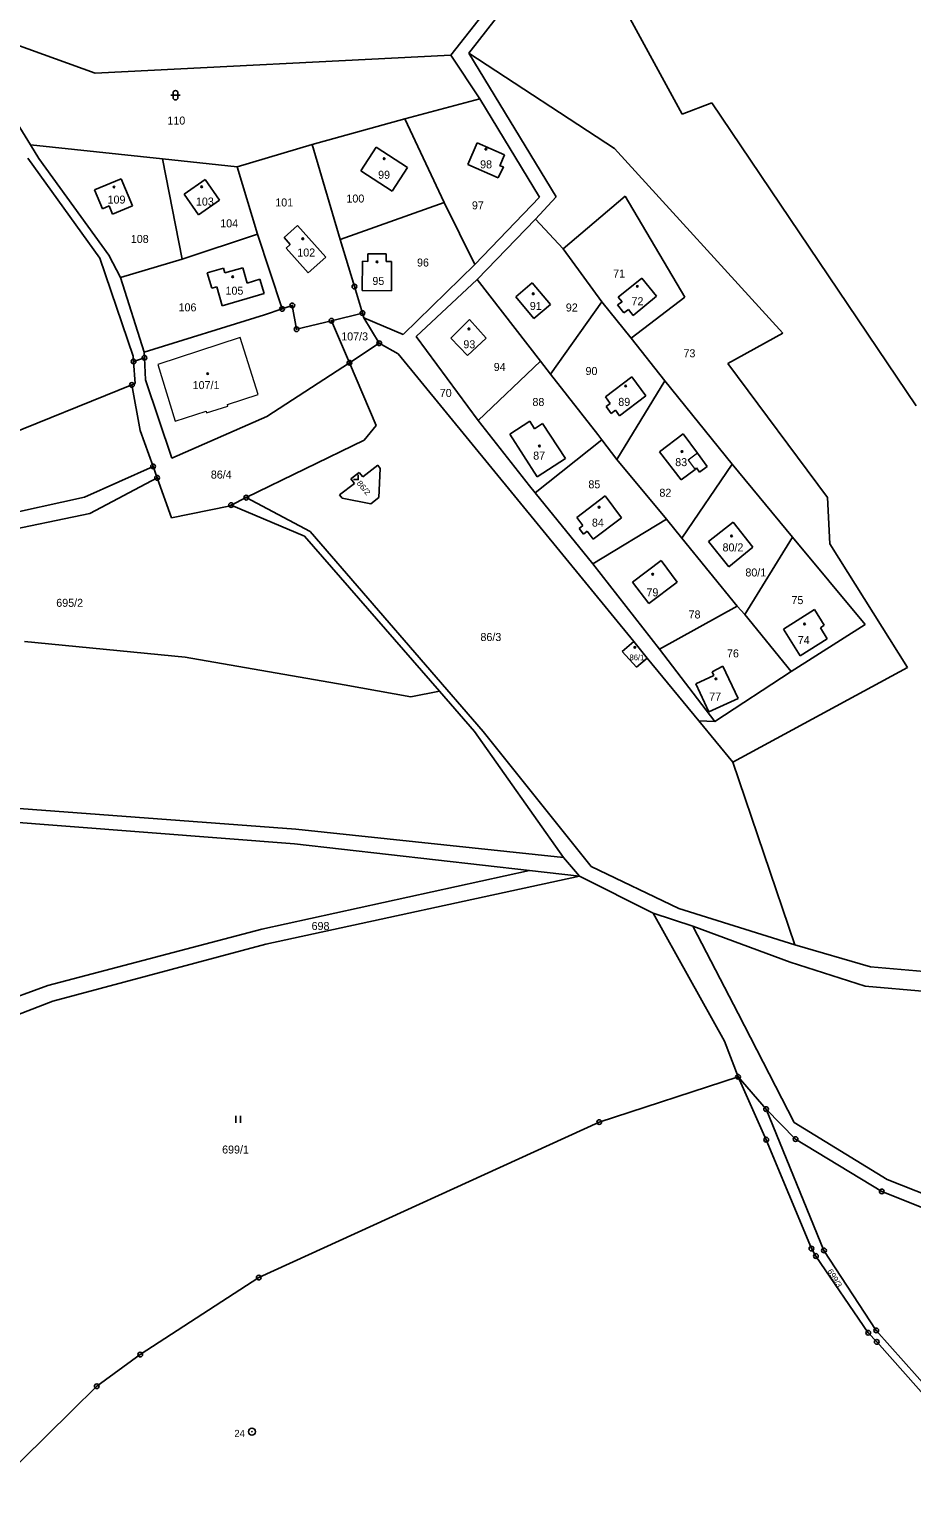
# Model space of a CAD drawing. Extents: x -727701 to -724405, y -960481 to -957284.
# Drawn here: x -726246.1 to -726058.6, y -958595.3 to -958285.9 of the extents above; entities that cross this region are included whole.
import ezdxf
from ezdxf.enums import TextEntityAlignment as Align

# ---------------------------------------------------------------- set-up
doc = ezdxf.new("R2010")
doc.units = 0
doc.header["$LTSCALE"] = 0.68
for name, color, linetype, lineweight in [('1', 7, 'Continuous', 25), ('3', 7, 'Continuous', 25), ('4', 7, 'Continuous', 13), ('5', 7, 'Continuous', 25), ('8', 7, 'Continuous', 25)]:
    doc.layers.add(name, color=color, linetype=linetype, lineweight=lineweight)
doc.layers.add('2', color=7, linetype='Continuous')

msp = doc.modelspace()

# ---------------------------------------------------------------- linework, layer by layer
at = {"layer": '1'}
for p, q in [((-726156.53, -958291.46), (-726131.48, -958259.62)), ((-726130.22, -958262.09), (-726152.69, -958291.05)), ((-726107.42, -958304.01), (-726130.22, -958262.09)), ((-726248.92, -958289.17), (-726232.04, -958295.26)), ((-726232.04, -958295.26), (-726156.53, -958291.46)), ((-726156.53, -958291.46), (-726150.4, -958300.7)), ((-726152.69, -958291.05), (-726121.8, -958311.26)), ((-726152.69, -958291.05), (-726134.14, -958321.53)), ((-726252.3, -958300), (-726245.81, -958310.48)), ((-726150.4, -958300.7), (-726166.3, -958305)), ((-726150.4, -958300.7), (-726137.68, -958321.61)), ((-726101.1, -958301.58), (-726107.42, -958304.01)), ((-726101.1, -958301.58), (-726057.73, -958365.9)), ((-726166.3, -958305), (-726186, -958310.45)), ((-726166.3, -958305), (-726157.97, -958322.75)), ((-726245.81, -958310.48), (-726244, -958313.4)), ((-726245.81, -958310.48), (-726217.76, -958313.46)), ((-726186, -958310.45), (-726201.9, -958315.15)), ((-726186, -958310.45), (-726180, -958330.6)), ((-726152.95, -958314.7), (-726150.95, -958310.05)), ((-726150.95, -958310.05), (-726145.15, -958312.65)), ((-726231.1, -958334.55), (-726246.35, -958313.35)), ((-726244, -958313.4), (-726229.15, -958333.9)), ((-726217.76, -958313.46), (-726201.9, -958315.15)), ((-726217.76, -958313.46), (-726213.61, -958334.79)), ((-726175.66, -958316.02), (-726172.41, -958310.97)), ((-726172.41, -958310.97), (-726165.71, -958315.28)), ((-726145.15, -958312.65), (-726146.15, -958314.95)), ((-726121.8, -958311.26), (-726086.04, -958350.49)), ((-726201.9, -958315.15), (-726197.62, -958329.45)), ((-726168.96, -958320.33), (-726175.66, -958316.02)), ((-726165.71, -958315.28), (-726168.96, -958320.33)), ((-726146.45, -958317.5), (-726152.95, -958314.7)), ((-726145.35, -958315.2), (-726146.45, -958317.5)), ((-726146.15, -958314.95), (-726145.35, -958315.2)), ((-726232.17, -958320.08), (-726226.53, -958317.72)), ((-726226.53, -958317.72), (-726224.12, -958323.47)), ((-726213.18, -958320.94), (-726208.73, -958317.88)), ((-726208.73, -958317.88), (-726205.69, -958322.28)), ((-726230.51, -958324.06), (-726232.17, -958320.08)), ((-726210.14, -958325.35), (-726213.18, -958320.94)), ((-726205.69, -958322.28), (-726210.14, -958325.35)), ((-726180, -958330.6), (-726157.97, -958322.75)), ((-726157.97, -958322.75), (-726151.46, -958335.91)), ((-726137.68, -958321.61), (-726151.46, -958335.91)), ((-726134.14, -958321.53), (-726138.53, -958326.25)), ((-726132.7, -958332.6), (-726119.48, -958321.37)), ((-726119.48, -958321.37), (-726106.86, -958342.85)), ((-726229.12, -958323.47), (-726230.51, -958324.06)), ((-726228.38, -958325.25), (-726229.12, -958323.47)), ((-726224.12, -958323.47), (-726228.38, -958325.25)), ((-726191.95, -958330.16), (-726189.12, -958327.62)), ((-726189.12, -958327.62), (-726183.1, -958334.34)), ((-726138.53, -958326.25), (-726150.93, -958339.1)), ((-726138.53, -958326.25), (-726132.7, -958332.6)), ((-726197.62, -958329.45), (-726213.61, -958334.79)), ((-726192.38, -958345.35), (-726197.62, -958329.45)), ((-726190.62, -958331.65), (-726191.95, -958330.16)), ((-726191.51, -958332.45), (-726190.62, -958331.65)), ((-726177, -958340.6), (-726180, -958330.6)), ((-726224, -958355.35), (-726231.1, -958334.55)), ((-726229.15, -958333.9), (-726226.71, -958338.7)), ((-726213.61, -958334.79), (-726226.71, -958338.7)), ((-726186.83, -958337.68), (-726191.51, -958332.45)), ((-726183.1, -958334.34), (-726186.83, -958337.68)), ((-726175.34, -958341.45), (-726175.31, -958335.23)), ((-726175.31, -958335.23), (-726174.17, -958335.24)), ((-726174.17, -958335.24), (-726174.16, -958333.65)), ((-726174.16, -958333.65), (-726170.29, -958333.67)), ((-726170.29, -958333.67), (-726170.29, -958335.26)), ((-726170.29, -958335.26), (-726169.1, -958335.27)), ((-726169.1, -958335.27), (-726169.13, -958341.48)), ((-726132.7, -958332.6), (-726124.5, -958343.85)), ((-726208.24, -958337.69), (-726204.81, -958336.7)), ((-726207.3, -958340.96), (-726208.24, -958337.69)), ((-726204.81, -958336.7), (-726204.52, -958337.7)), ((-726204.52, -958337.7), (-726200.72, -958336.6)), ((-726200.72, -958336.6), (-726199.78, -958339.85)), ((-726151.46, -958335.91), (-726166.67, -958350.8)), ((-726226.71, -958338.7), (-726221.66, -958354.51)), ((-726206.23, -958340.65), (-726207.3, -958340.96)), ((-726205.07, -958344.66), (-726206.23, -958340.65)), ((-726199.78, -958339.85), (-726197.06, -958339.06)), ((-726197.06, -958339.06), (-726196.19, -958342.09)), ((-726177, -958340.6), (-726175.31, -958346.24)), ((-726169.13, -958341.48), (-726175.34, -958341.45)), ((-726150.93, -958339.1), (-726163.91, -958351.18)), ((-726150.93, -958339.1), (-726137.5, -958356.45)), ((-726142.75, -958342.8), (-726139.23, -958339.84)), ((-726139.23, -958339.84), (-726135.36, -958344.43)), ((-726120.97, -958342.84), (-726116, -958338.8)), ((-726116, -958338.8), (-726112.85, -958342.67)), ((-726196.19, -958342.09), (-726205.07, -958344.66)), ((-726192.38, -958345.35), (-726190.19, -958344.6)), ((-726189.3, -958349.67), (-726190.19, -958344.6)), ((-726138.88, -958347.39), (-726142.75, -958342.8)), ((-726135.36, -958344.43), (-726138.88, -958347.39)), ((-726135.35, -958359.2), (-726124.5, -958343.85)), ((-726124.5, -958343.85), (-726118.26, -958351.56)), ((-726121.16, -958344.51), (-726120.14, -958343.85)), ((-726119.81, -958346.16), (-726121.16, -958344.51)), ((-726120.14, -958343.85), (-726120.97, -958342.84)), ((-726106.86, -958342.85), (-726118.26, -958351.56)), ((-726112.85, -958342.67), (-726117.81, -958346.71)), ((-726221.66, -958354.51), (-726196.07, -958346.62)), ((-726196.07, -958346.62), (-726192.38, -958345.35)), ((-726175.31, -958346.24), (-726181.88, -958347.85)), ((-726175.31, -958346.24), (-726175.01, -958347.25)), ((-726175.01, -958347.25), (-726171.72, -958352.65)), ((-726166.67, -958350.8), (-726175.01, -958347.25)), ((-726156.5, -958351.55), (-726152.6, -958347.6)), ((-726152.6, -958347.6), (-726149.05, -958351.55)), ((-726118.82, -958345.47), (-726119.81, -958346.16)), ((-726117.81, -958346.71), (-726118.82, -958345.47)), ((-726181.88, -958347.85), (-726189.3, -958349.67)), ((-726178.07, -958356.78), (-726181.88, -958347.85)), ((-726086.04, -958350.49), (-726097.7, -958356.93)), ((-726171.72, -958352.65), (-726178.07, -958356.78)), ((-726171.72, -958352.65), (-726167.68, -958354.91)), ((-726163.91, -958351.18), (-726150.74, -958369.06)), ((-726153, -958355.25), (-726156.5, -958351.55)), ((-726149.05, -958351.55), (-726153, -958355.25)), ((-726118.26, -958351.56), (-726111.1, -958360.6)), ((-726223.91, -958356.5), (-726224, -958355.35)), ((-726221.61, -958355.72), (-726223.91, -958356.5)), ((-726223.55, -958361.2), (-726223.91, -958356.5)), ((-726221.66, -958354.51), (-726221.61, -958355.72)), ((-726221.61, -958355.72), (-726221.4, -958360.4)), ((-726195.6, -958368.19), (-726178.07, -958356.78)), ((-726172.38, -958370.12), (-726178.07, -958356.78)), ((-726117.66, -958416.01), (-726167.68, -958354.91)), ((-726137.5, -958356.45), (-726150.74, -958369.06)), ((-726137.5, -958356.45), (-726135.35, -958359.2)), ((-726097.7, -958356.93), (-726076.55, -958385.41)), ((-726135.35, -958359.2), (-726125.35, -958372.05)), ((-726123.71, -958364.02), (-726118.13, -958359.79)), ((-726118.13, -958359.79), (-726115.1, -958363.79)), ((-726224.26, -958361.49), (-726337.66, -958407.23)), ((-726224.26, -958361.49), (-726223.55, -958361.2)), ((-726222.49, -958371.17), (-726224.26, -958361.49)), ((-726221.4, -958360.4), (-726215.76, -958377.07)), ((-726121.3, -958377.3), (-726111.1, -958360.6)), ((-726111.1, -958360.6), (-726096.8, -958378.3)), ((-726122.67, -958365.4), (-726123.71, -958364.02)), ((-726123.58, -958366.09), (-726122.67, -958365.4)), ((-726122.49, -958367.54), (-726123.58, -958366.09)), ((-726115.1, -958363.79), (-726120.68, -958368.02)), ((-726195.6, -958368.19), (-726215.76, -958377.07)), ((-726150.74, -958369.06), (-726139.8, -958382.9)), ((-726144, -958371.96), (-726139.78, -958369.15)), ((-726139.78, -958369.15), (-726138.73, -958370.8)), ((-726121.57, -958366.84), (-726122.49, -958367.54)), ((-726120.68, -958368.02), (-726121.57, -958366.84)), ((-726222.49, -958371.17), (-726219.77, -958378.79)), ((-726174.91, -958373.24), (-726172.38, -958370.12)), ((-726138.17, -958381), (-726144, -958371.96)), ((-726138.73, -958370.8), (-726137.07, -958369.7)), ((-726137.07, -958369.7), (-726132.21, -958377.13)), ((-726125.35, -958372.05), (-726124.48, -958373.17)), ((-726112.21, -958375.72), (-726107.21, -958371.86)), ((-726107.21, -958371.86), (-726104.16, -958375.95)), ((-726199.96, -958385.43), (-726174.91, -958373.24)), ((-726124.48, -958373.17), (-726138.61, -958384.37)), ((-726124.48, -958373.17), (-726121.3, -958377.3)), ((-726175.25, -958381.02), (-726172.05, -958378.53)), ((-726172.05, -958378.53), (-726171.51, -958379.23)), ((-726132.21, -958377.13), (-726138.17, -958381)), ((-726121.3, -958377.3), (-726110.75, -958390)), ((-726112.21, -958375.72), (-726107.63, -958381.65)), ((-726107.5, -958394.05), (-726096.8, -958378.3)), ((-726104.16, -958375.95), (-726102.07, -958378.79)), ((-726096.8, -958378.3), (-726083.95, -958393.8)), ((-726234.32, -958385.34), (-726219.77, -958378.79)), ((-726218.9, -958381.22), (-726233.19, -958388.78)), ((-726219.77, -958378.79), (-726218.9, -958381.22)), ((-726218.9, -958381.22), (-726215.86, -958389.72)), ((-726177.75, -958381.45), (-726175.99, -958380.07)), ((-726177, -958382.45), (-726177.75, -958381.45)), ((-726175.99, -958380.07), (-726175.25, -958381.02)), ((-726171.84, -958385.42), (-726171.51, -958379.23)), ((-726104.65, -958379.42), (-726107.63, -958381.65)), ((-726104.35, -958379.13), (-726104.65, -958379.42)), ((-726103.71, -958380), (-726104.35, -958379.13)), ((-726102.07, -958378.79), (-726103.71, -958380)), ((-726180.16, -958384.84), (-726177, -958382.45)), ((-726139.8, -958382.9), (-726138.61, -958384.37)), ((-726138.61, -958384.37), (-726126.4, -958399.45)), ((-726275.59, -958394.37), (-726234.32, -958385.34)), ((-726215.86, -958389.72), (-726203.69, -958387.24)), ((-726203.69, -958387.24), (-726203.2, -958387)), ((-726203.2, -958387), (-726199.96, -958385.43)), ((-726203.2, -958387), (-726187.6, -958393.6)), ((-726186.4, -958392.6), (-726199.96, -958385.43)), ((-726179.62, -958385.54), (-726180.16, -958384.84)), ((-726173.55, -958386.75), (-726179.62, -958385.54)), ((-726171.84, -958385.42), (-726173.55, -958386.75)), ((-726129.8, -958389.63), (-726123.76, -958385.07)), ((-726123.76, -958385.07), (-726120.27, -958389.7)), ((-726076.55, -958385.41), (-726076.03, -958395.25)), ((-726274.62, -958397.41), (-726233.19, -958388.78)), ((-726128.49, -958391.37), (-726129.8, -958389.63)), ((-726110.75, -958390), (-726126.4, -958399.45)), ((-726120.27, -958389.7), (-726126.32, -958394.26)), ((-726110.75, -958390), (-726107.5, -958394.05)), ((-726101.83, -958394.76), (-726096.57, -958390.61)), ((-726096.57, -958390.61), (-726092.38, -958395.92)), ((-726158.93, -958426.55), (-726187.6, -958393.6)), ((-726186.4, -958392.6), (-726149.7, -958435.1)), ((-726129.25, -958391.95), (-726128.49, -958391.37)), ((-726128.34, -958393.15), (-726129.25, -958391.95)), ((-726127.59, -958392.58), (-726128.34, -958393.15)), ((-726126.32, -958394.26), (-726127.59, -958392.58)), ((-726094.1, -958410.25), (-726083.95, -958393.8)), ((-726083.95, -958393.8), (-726068.53, -958412.38)), ((-726097.5, -958400.09), (-726101.83, -958394.76)), ((-726092.38, -958395.92), (-726097.5, -958400.09)), ((-726076.03, -958395.25), (-726059.53, -958421.51)), ((-726126.4, -958399.45), (-726112.25, -958417.6)), ((-726117.94, -958403.35), (-726111.9, -958398.81)), ((-726111.9, -958398.81), (-726108.45, -958403.4)), ((-726114.49, -958407.94), (-726117.94, -958403.35)), ((-726108.45, -958403.4), (-726114.49, -958407.94)), ((-726095.7, -958408.5), (-726112.25, -958417.6)), ((-726085.92, -958413.33), (-726079.34, -958409.19)), ((-726079.34, -958409.19), (-726077.23, -958412.54)), ((-726094.1, -958410.25), (-726084.25, -958422.35)), ((-726068.53, -958412.38), (-726084.25, -958422.35)), ((-726077.23, -958412.54), (-726078.05, -958413.06)), ((-726082.34, -958419.02), (-726085.92, -958413.33)), ((-726076.58, -958415.39), (-726082.34, -958419.02)), ((-726078.05, -958413.06), (-726076.58, -958415.39)), ((-726247.04, -958415.98), (-726212.97, -958419.3)), ((-726120.12, -958418.12), (-726117.13, -958421.41)), ((-726112.25, -958417.6), (-726100.5, -958433)), ((-726212.97, -958419.3), (-726179.17, -958425.18)), ((-726117.13, -958421.41), (-726114.81, -958419.49)), ((-726103.9, -958432.82), (-726114.81, -958419.49)), ((-726101.05, -958422.45), (-726098.8, -958421.25)), ((-726098.8, -958421.25), (-726095.55, -958428.05)), ((-726059.53, -958421.51), (-726096.68, -958441.64)), ((-726104.5, -958425), (-726100.7, -958423.2)), ((-726101.75, -958430.9), (-726104.5, -958425)), ((-726100.7, -958423.2), (-726101.05, -958422.45)), ((-726084.25, -958422.35), (-726100.5, -958433)), ((-726179.17, -958425.18), (-726165, -958427.74)), ((-726165, -958427.74), (-726158.93, -958426.55)), ((-726151.5, -958435.1), (-726158.93, -958426.55)), ((-726095.55, -958428.05), (-726101.75, -958430.9)), ((-726100.5, -958433), (-726103.9, -958432.82)), ((-726103.9, -958432.82), (-726096.68, -958441.64)), ((-726132.6, -958461.85), (-726151.5, -958435.1)), ((-726149.7, -958435.1), (-726126.7, -958463.75)), ((-726096.68, -958441.64), (-726083.49, -958480.39)), ((-726270.02, -958452.75), (-726189.71, -958458.93)), ((-726269.95, -958449.87), (-726189.48, -958455.81)), ((-726189.48, -958455.81), (-726132.6, -958461.85)), ((-726189.71, -958458.93), (-726139.8, -958464.6)), ((-726129.2, -958465.8), (-726132.6, -958461.85)), ((-726196.69, -958477.04), (-726139.8, -958464.6)), ((-726139.8, -958464.6), (-726129.2, -958465.8)), ((-726126.7, -958463.75), (-726108.1, -958472.7)), ((-726195.8, -958480.24), (-726129.2, -958465.8)), ((-726113.53, -958473.7), (-726129.2, -958465.8)), ((-726105.12, -958476.47), (-726113.53, -958473.7)), ((-726113.53, -958473.7), (-726098.44, -958500.89)), ((-726108.1, -958472.7), (-726083.49, -958480.39)), ((-726242.11, -958489.04), (-726196.69, -958477.04)), ((-726084.44, -958484.07), (-726105.12, -958476.47)), ((-726105.12, -958476.47), (-726095.52, -958494.99)), ((-726241.06, -958492.4), (-726195.8, -958480.24)), ((-726083.49, -958480.39), (-726067.38, -958485.05)), ((-726084.44, -958484.07), (-726068.57, -958489.21)), ((-726067.38, -958485.05), (-726056.01, -958486.05)), ((-726283.28, -958504.07), (-726242.11, -958489.04)), ((-726068.57, -958489.21), (-726055.6, -958490.29)), ((-726281.59, -958507.9), (-726241.06, -958492.4)), ((-726095.52, -958494.99), (-726083.59, -958518.15)), ((-726098.44, -958500.89), (-726095.55, -958508.42)), ((-726125.02, -958518.05), (-726095.55, -958508.42)), ((-726095.55, -958508.42), (-726089.59, -958515.3)), ((-726095.55, -958508.42), (-726089.56, -958521.78)), ((-726089.59, -958515.3), (-726077.29, -958545.31)), ((-726089.59, -958515.3), (-726083.33, -958521.66)), ((-726197.31, -958551.06), (-726125.02, -958518.05)), ((-726083.59, -958518.15), (-726063.89, -958530.24)), ((-726089.56, -958521.78), (-726079.97, -958544.9)), ((-726083.33, -958521.66), (-726065.02, -958532.76)), ((-726063.89, -958530.24), (-726026.96, -958544.77)), ((-726065.02, -958532.76), (-726028.67, -958547.43)), ((-726079.97, -958544.9), (-726079.01, -958546.49)), ((-726077.29, -958545.31), (-726066.19, -958562.28)), ((-726079.01, -958546.49), (-726067.9, -958562.78)), ((-726222.49, -958567.41), (-726197.31, -958551.06)), ((-726067.9, -958562.78), (-726066.08, -958564.72)), ((-726066.19, -958562.28), (-726044.96, -958586.2)), ((-726066.08, -958564.72), (-726044.64, -958588.99)), ((-726231.71, -958574.16), (-726222.49, -958567.41)), ((-726273.58, -958615.43), (-726231.71, -958574.16))]:
    msp.add_line(p, q, dxfattribs=at)
for points in [[(-726107.5, -958394.05), (-726095.7, -958408.5), (-726094.1, -958410.25)], [(-726114.81, -958419.49), (-726117.66, -958416.01), (-726120.12, -958418.12)]]:
    msp.add_lwpolyline(points, dxfattribs=at)
at = {"layer": '3'}
for p, q in [((-726216.001, -958299.961), (-726213.999, -958299.961)), ((-726215.501, -958299.461), (-726215.501, -958300.462)), ((-726214.499, -958300.462), (-726214.499, -958299.461)), ((-726202.201, -958518.21), (-726202.201, -958516.71)), ((-726201.2, -958518.21), (-726201.2, -958516.71))]:
    msp.add_line(p, q, dxfattribs=at)
msp.add_lwpolyline([(-726177.191, -958381.59), (-726176.19, -958381.59), (-726176.19, -958380.59)], dxfattribs=at)
for centre, start, end in [((-726215, -958299.4609), 0, 180), ((-726215, -958300.4609), 180, 359.98789)]:
    msp.add_arc(centre, 0.5, start, end, dxfattribs=at)
at = {"layer": '4'}
for p, q in [((-726201.28, -958351.44), (-726218.78, -958357.13)), ((-726197.43, -958363.53), (-726201.28, -958351.44)), ((-726218.78, -958357.13), (-726215.06, -958369.17)), ((-726208.41, -958367.38), (-726203.89, -958365.99)), ((-726203.99, -958365.63), (-726197.43, -958363.53)), ((-726203.89, -958365.99), (-726203.99, -958365.63)), ((-726215.06, -958369.17), (-726208.51, -958367.08)), ((-726208.51, -958367.08), (-726208.41, -958367.38)), ((-726104.16, -958375.95), (-726106.16, -958377.46)), ((-726106.16, -958377.46), (-726104.65, -958379.42))]:
    msp.add_line(p, q, dxfattribs=at)
at = {"layer": '5'}
for centre in [(-726170.6868, -958313.4492), (-726149.0968, -958311.4192), (-726228.0768, -958319.4592), (-726209.4368, -958319.4092), (-726187.9768, -958330.4492), (-726172.2168, -958335.3592), (-726202.8768, -958338.5192), (-726116.9168, -958340.5492), (-726139.0368, -958342.1392), (-726152.6968, -958349.5792), (-726208.1568, -958359.0892), (-726119.4068, -958361.6992), (-726137.7068, -958374.4692), (-726107.4368, -958375.6292), (-726125.0368, -958387.4592), (-726096.9268, -958393.5592), (-726113.6868, -958401.6892), (-726081.4168, -958412.2592), (-726117.4568, -958417.2292), (-726100.2468, -958423.9092)]:
    msp.add_circle(centre, 0.175, dxfattribs=at)
at = {"layer": '8'}
for centre, radius in [((-726177, -958340.5999), 0.5), ((-726177, -958340.5999), 0.0303), ((-726190.19, -958344.5999), 0.5), ((-726190.19, -958344.5999), 0.0303), ((-726192.38, -958345.3499), 0.5), ((-726192.38, -958345.3499), 0.0303), ((-726181.88, -958347.8499), 0.5), ((-726175.31, -958346.2399), 0.5), ((-726175.31, -958346.2399), 0.0303), ((-726189.3, -958349.6699), 0.5), ((-726189.3, -958349.6699), 0.0303), ((-726181.88, -958347.8499), 0.0303), ((-726171.72, -958352.6499), 0.5), ((-726171.72, -958352.6499), 0.0303), ((-726223.91, -958356.4999), 0.5), ((-726223.91, -958356.4999), 0.0303), ((-726221.61, -958355.7199), 0.5), ((-726221.61, -958355.7199), 0.0303), ((-726178.07, -958356.7799), 0.5), ((-726178.07, -958356.7799), 0.0303), ((-726224.26, -958361.4899), 0.5), ((-726224.26, -958361.4899), 0.0303), ((-726219.77, -958378.7899), 0.5), ((-726219.77, -958378.7899), 0.0303), ((-726218.9, -958381.2199), 0.5), ((-726218.9, -958381.2199), 0.0303), ((-726203.2, -958386.9999), 0.5), ((-726203.2, -958386.9999), 0.0303), ((-726199.96, -958385.4299), 0.5), ((-726199.96, -958385.4299), 0.0303), ((-726095.55, -958508.4199), 0.5), ((-726095.55, -958508.4199), 0.0303), ((-726125.02, -958518.0499), 0.5), ((-726089.59, -958515.2999), 0.5), ((-726089.59, -958515.2999), 0.0303), ((-726125.02, -958518.0499), 0.0303), ((-726089.56, -958521.7799), 0.5), ((-726089.56, -958521.7799), 0.0303), ((-726083.33, -958521.6599), 0.5), ((-726083.33, -958521.6599), 0.0303), ((-726065.02, -958532.7599), 0.5), ((-726065.02, -958532.7599), 0.0303), ((-726079.97, -958544.8999), 0.5), ((-726079.97, -958544.8999), 0.0303), ((-726077.29, -958545.3099), 0.5), ((-726077.29, -958545.3099), 0.0303), ((-726079.01, -958546.4899), 0.5), ((-726079.01, -958546.4899), 0.0303), ((-726197.31, -958551.0599), 0.5), ((-726197.31, -958551.0599), 0.0303), ((-726067.9, -958562.7799), 0.5), ((-726067.9, -958562.7799), 0.0303), ((-726066.19, -958562.2799), 0.5), ((-726066.08, -958564.7199), 0.5), ((-726066.19, -958562.2799), 0.0303), ((-726222.49, -958567.4099), 0.5), ((-726066.08, -958564.7199), 0.0303), ((-726222.49, -958567.4099), 0.0303), ((-726231.71, -958574.1599), 0.5), ((-726231.71, -958574.1599), 0.0303), ((-726198.77, -958583.7998), 0.75), ((-726198.77, -958583.7998), 0.03)]:
    msp.add_circle(centre, radius, dxfattribs=at)

# ---------------------------------------------------------------- texts
at = {"layer": '2'}
for s, height, p in [('110', 1.7, (-726216.72, -958306.195)), ('99', 1.7, (-726171.97, -958317.705)), ('98', 1.7, (-726150.31, -958315.495)), ('109', 1.7, (-726229.42, -958322.975)), ('103', 1.7, (-726210.66, -958323.395)), ('101', 1.7, (-726193.81, -958323.585)), ('100', 1.7, (-726178.7, -958322.755)), ('97', 1.7, (-726152.05, -958324.195)), ('104', 1.7, (-726205.5, -958328.025)), ('108', 1.7, (-726224.49, -958331.335)), ('102', 1.7, (-726189.13, -958334.215)), ('96', 1.7, (-726163.71, -958336.345)), ('71', 1.7, (-726122.06, -958338.675)), ('105', 1.7, (-726204.38, -958342.325)), ('95', 1.7, (-726173.19, -958340.255)), ('106', 1.7, (-726214.35, -958345.865)), ('91', 1.7, (-726139.76, -958345.565)), ('92', 1.7, (-726132.11, -958345.895)), ('72', 1.7, (-726118.16, -958344.565)), ('93', 1.7, (-726153.87, -958353.705)), ('73', 1.7, (-726107.13, -958355.615)), ('94', 1.7, (-726147.42, -958358.525)), ('90', 1.7, (-726127.93, -958359.385)), ('70', 1.7, (-726158.88, -958364.045)), ('88', 1.7, (-726139.2, -958365.955)), ('89', 1.7, (-726120.97, -958365.935)), ('83', 1.7, (-726108.88, -958378.735)), ('85', 1.7, (-726127.32, -958383.445)), ('82', 1.7, (-726112.24, -958385.235)), ('84', 1.7, (-726126.57, -958391.575)), ('79', 1.7, (-726114.99, -958406.385)), ('75', 1.7, (-726084.2, -958408.035)), ('695/2', 1.7, (-726240.32, -958408.615)), ('78', 1.7, (-726106.04, -958411.085)), ('86/3', 1.7, (-726150.24, -958415.875)), ('74', 1.7, (-726082.86, -958416.515)), ('86/1', 1.2, (-726118.58, -958419.95)), ('76', 1.7, (-726097.89, -958419.355)), ('77', 1.7, (-726101.67, -958428.535)), ('698', 1.7, (-726186.1, -958477.245)), ('699/1', 1.7, (-726205.1, -958524.725))]:
    msp.add_text(s, height=height, dxfattribs=at).set_placement(p)
for s, p in [('107/3', (-726176.96, -958352.035)), ('107/1', (-726208.51, -958362.375)), ('87', (-726137.779, -958377.345)), ('86/4', (-726205.279, -958381.375)), ('80/2', (-726096.619, -958396.845)), ('80/1', (-726091.769, -958402.165))]:
    msp.add_text(s, height=1.7, dxfattribs=at).set_placement(p, align=Align.CENTER)
for s, rotation, width, p in [('86/2', 310, 1.1, (-726176.599, -958382.412)), ('699/3', 302, 1.05, (-726076.624, -958549.718))]:
    msp.add_text(s, height=1.2, rotation=rotation, dxfattribs=dict(at, width=width)).set_placement(p)
at = {"layer": '8'}
msp.add_text('24', height=1.5, dxfattribs=at).set_placement((-726200.269, -958584.917), align=Align.RIGHT)

doc.saveas('drawing.dxf')
